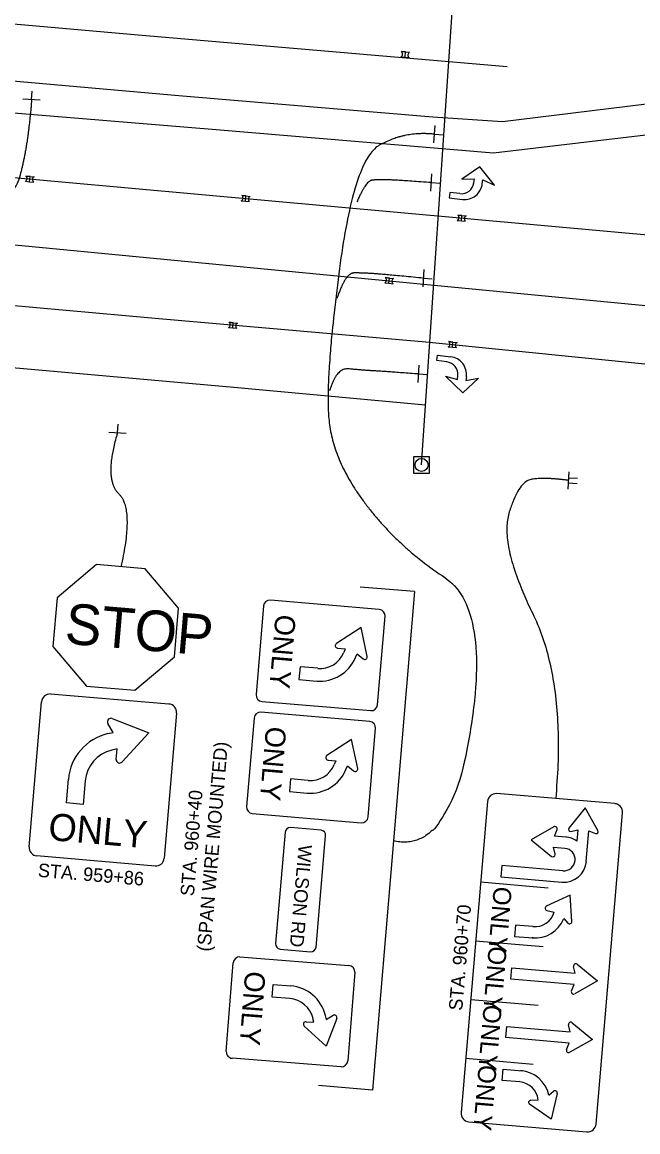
# Model space of a CAD drawing. Extents: x 1847379 to 1850904, y 217032 to 220169.
# Drawn here: x 1850096.6 to 1850210.2, y 218575.8 to 218780.5 of the extents above; entities that cross this region are included whole.
import ezdxf

# ---------------------------------------------------------------- set-up
doc = ezdxf.new("R2010")
doc.units = 0
for name, color, linetype in [('PM_P_Cells', 7, 'Continuous'), ('PM_P_Channelizing_Line', 7, 'Continuous'), ('PM_P_Edge_Line', 7, 'Continuous'), ('PM_P_Lane_Line', 7, 'Continuous'), ('SG_X_Poles', 7, 'Continuous'), ('SN_X_Public', 7, 'Continuous'), ('SN_X_Text', 7, 'Continuous')]:
    doc.layers.add(name, color=color, linetype=linetype)

msp = doc.modelspace()

# ---------------------------------------------------------------- linework, layer by layer
at = {"layer": 'PM_P_Cells'}
for p, q in [((1850166.51, 218774.14), (1850167.28, 218774.07)), ((1850166.51, 218774.14), (1850167.28, 218774.07)), ((1850167.36, 218775.04), (1850166.6, 218775.11)), ((1850166.6, 218775.11), (1850167.36, 218775.04)), ((1850167.28, 218774.07), (1850167.36, 218775.04)), ((1850167.28, 218774.07), (1850168.04, 218774)), ((1850167.36, 218775.04), (1850168.13, 218774.98)), ((1850181.1, 218753.83), (1850177.76, 218751.54)), ((1850183.76, 218750.49), (1850181.1, 218753.83)), ((1850098.09, 218752.07), (1850097.32, 218752.14)), ((1850097.32, 218752.14), (1850098.09, 218752.07)), ((1850098, 218751.1), (1850098.09, 218752.07)), ((1850098.09, 218752.07), (1850098.85, 218752)), ((1850175.82, 218751.44), (1850175.82, 218751.44)), ((1850177.76, 218751.54), (1850180.03, 218751.61)), ((1850180.03, 218751.61), (1850179.94, 218750.91)), ((1850097.23, 218751.17), (1850098, 218751.1)), ((1850097.23, 218751.17), (1850098, 218751.1)), ((1850098, 218751.1), (1850098.77, 218751.03)), ((1850181.53, 218750.75), (1850181.61, 218751.42)), ((1850181.61, 218751.42), (1850183.76, 218750.49)), ((1850183.76, 218750.49), (1850183.76, 218750.49)), ((1850137.07, 218747.57), (1850137.84, 218747.5)), ((1850137.07, 218747.57), (1850137.84, 218747.5)), ((1850137.93, 218748.47), (1850137.16, 218748.54)), ((1850137.16, 218748.54), (1850137.93, 218748.47)), ((1850137.84, 218747.5), (1850137.93, 218748.47)), ((1850137.84, 218747.5), (1850138.6, 218747.43)), ((1850137.93, 218748.47), (1850138.69, 218748.4)), ((1850175.54, 218749.12), (1850175.42, 218748.13)), ((1850175.42, 218748.13), (1850177.88, 218747.83)), ((1850177.39, 218748.9), (1850175.54, 218749.12)), ((1850176.91, 218743.96), (1850177.68, 218743.89)), ((1850176.91, 218743.96), (1850177.68, 218743.89)), ((1850177.76, 218744.87), (1850177, 218744.94)), ((1850177, 218744.94), (1850177.76, 218744.87)), ((1850177.68, 218743.89), (1850177.76, 218744.87)), ((1850177.68, 218743.89), (1850178.44, 218743.82)), ((1850177.76, 218744.87), (1850178.53, 218744.8)), ((1850164.39, 218733.33), (1850163.63, 218733.4)), ((1850163.63, 218733.4), (1850164.39, 218733.33)), ((1850164.31, 218732.35), (1850164.39, 218733.33)), ((1850164.39, 218733.33), (1850165.16, 218733.26)), ((1850163.54, 218732.42), (1850164.31, 218732.35)), ((1850163.54, 218732.42), (1850164.31, 218732.35)), ((1850164.31, 218732.35), (1850165.07, 218732.28)), ((1850135.57, 218725.09), (1850134.81, 218725.16)), ((1850134.81, 218725.16), (1850135.57, 218725.09)), ((1850135.49, 218724.12), (1850135.57, 218725.09)), ((1850135.57, 218725.09), (1850136.34, 218725.02)), ((1850134.72, 218724.19), (1850135.49, 218724.12)), ((1850134.72, 218724.19), (1850135.49, 218724.12)), ((1850135.49, 218724.12), (1850136.25, 218724.05)), ((1850176.11, 218721.52), (1850175.34, 218721.59)), ((1850175.34, 218721.59), (1850176.11, 218721.52)), ((1850176.02, 218720.55), (1850176.11, 218721.52)), ((1850176.11, 218721.52), (1850176.88, 218721.45)), ((1850173.14, 218718.08), (1850173.26, 218719.07)), ((1850173.26, 218719.07), (1850175.72, 218718.79)), ((1850175.25, 218720.62), (1850176.02, 218720.55)), ((1850175.25, 218720.62), (1850176.02, 218720.55)), ((1850176.02, 218720.55), (1850176.79, 218720.48)), ((1850174.99, 218717.86), (1850173.14, 218718.08)), ((1850172.88, 218715.76), (1850172.88, 218715.76)), ((1850177.94, 218712.16), (1850174.74, 218715.21)), ((1850174.74, 218715.21), (1850176.93, 218714.62)), ((1850176.93, 218714.62), (1850177.01, 218715.32)), ((1850180.82, 218714.85), (1850177.94, 218712.16)), ((1850178.6, 218715.1), (1850178.52, 218714.44)), ((1850178.52, 218714.44), (1850180.82, 218714.85)), ((1850180.82, 218714.85), (1850180.82, 218714.85))]:
    msp.add_line(p, q, dxfattribs=at)
for centre, radius, start, end in [((1850166.25, 218774.66), 0.576, 296.8063, 52.8586), ((1850166.25, 218774.66), 0.576, 296.8063, 52.8586), ((1850168.39, 218774.46), 0.576, 116.8063, 232.8586), ((1850096.97, 218751.68), 0.576, 296.8063, 52.8586), ((1850096.97, 218751.68), 0.576, 296.8063, 52.8586), ((1850099.11, 218751.49), 0.576, 116.8063, 232.8586), ((1850177.66, 218751.18), 2.3, 263.1824, 353.1824), ((1850178.27, 218751.09), 3.28, 263.1824, 354.0909), ((1850136.81, 218748.08), 0.576, 296.8063, 52.8586), ((1850136.81, 218748.08), 0.576, 296.8063, 52.8586), ((1850138.95, 218747.89), 0.576, 116.8063, 232.8586), ((1850176.65, 218744.48), 0.576, 296.8063, 52.8586), ((1850176.65, 218744.48), 0.576, 296.8063, 52.8586), ((1850178.79, 218744.28), 0.576, 116.8063, 232.8586), ((1850163.28, 218732.94), 0.576, 296.8063, 52.8586), ((1850163.28, 218732.94), 0.576, 296.8063, 52.8586), ((1850165.42, 218732.74), 0.576, 116.8063, 232.8586), ((1850134.46, 218724.7), 0.576, 296.8063, 52.8586), ((1850134.46, 218724.7), 0.576, 296.8063, 52.8586), ((1850136.6, 218724.51), 0.576, 116.8063, 232.8586), ((1850174.99, 218721.13), 0.576, 296.8063, 52.8586), ((1850174.99, 218721.13), 0.576, 296.8063, 52.8586), ((1850177.13, 218720.94), 0.576, 116.8063, 232.8586), ((1850175.34, 218715.53), 3.28, 352.5446, 83.453), ((1850174.73, 218715.58), 2.3, 353.453, 83.453)]:
    msp.add_arc(centre, radius, start, end, dxfattribs=at)
at = {"layer": 'PM_P_Channelizing_Line'}
for points in [[(1850652.98, 218698.12), (1850615.27, 218701.75), (1850564.66, 218706.78), (1850513.12, 218712.05), (1850461.3, 218717.14), (1850408.88, 218722.34), (1850360.86, 218727.03), (1850313.39, 218731.82), (1850265.8, 218736.37), (1849979.48, 218762.27)], [(1850650.65, 218674.09), (1850566.02, 218682.53), (1850518.02, 218687.39), (1850471.03, 218692.07), (1850419.06, 218697.16), (1850371.65, 218702.19), (1850311.6, 218707.75), (1850264.65, 218712.06), (1850215.84, 218717), (1850171.13, 218721.51), (1850121.19, 218725.85), (1850066.37, 218730.8), (1850014.99, 218735.41), (1849965.69, 218739.72), (1849914.21, 218744.36), (1849896.49, 218746.14)]]:
    msp.add_lwpolyline(points, dxfattribs=at)
at = {"layer": 'PM_P_Edge_Line'}
for p, q in [((1850068.7, 218772.02), (1850126.22, 218766.95)), ((1850185.27, 218762.22), (1850232.15, 218767.99)), ((1850126.22, 218766.95), (1850172.4, 218763.06)), ((1850132.45, 218760.65), (1850081.59, 218764.87)), ((1850172.4, 218763.06), (1850185.27, 218762.22)), ((1850235.11, 218762.44), (1850183.58, 218756.39)), ((1850183.58, 218756.39), (1850132.45, 218760.65))]:
    msp.add_line(p, q, dxfattribs=at)
msp.add_lwpolyline([(1849832.17, 218750.77), (1849894.17, 218734.94), (1849941.43, 218730.63), (1849992.34, 218726.14), (1850039.4, 218721.8), (1850086.44, 218717.54), (1850135.69, 218713.18), (1850171.07, 218709.94)], dxfattribs=at)
at = {"layer": 'PM_P_Lane_Line'}
msp.add_line((1849881.96, 218760.04), (1850650.78, 218685.87), dxfattribs=at)
msp.add_lwpolyline([(1849608.14, 218816.84), (1849659.46, 218813.21), (1849709.31, 218809.62), (1849760.21, 218805.9), (1849807.22, 218802.44), (1849857.63, 218799.12), (1849906.82, 218795.7), (1849957.46, 218791.82), (1850014.55, 218787.19), (1850067.13, 218782.71), (1850118.03, 218778.2), (1850167.47, 218773.95), (1850186.14, 218772.34)], dxfattribs=at)
at = {"layer": 'SG_X_Poles'}
msp.add_lwpolyline([(1850168.82, 218697.33), (1850171.82, 218697.33), (1850171.82, 218700.33), (1850168.82, 218700.33)], close=True, dxfattribs=at)
msp.add_circle((1850170.32, 218698.83), 1.2, dxfattribs=at)
at = {"layer": 'SN_X_Public'}
for p, q in [((1850170.32, 218698.83), (1850177.96, 218812.22)), ((1850098.38, 218766.24), (1850098.49, 218767.83)), ((1850099.98, 218766.13), (1850096.78, 218766.34)), ((1850172.61, 218758.27), (1850172.82, 218761.46)), ((1850172.72, 218759.86), (1850174.31, 218759.76)), ((1850172.03, 218749.33), (1850172.24, 218752.53)), ((1850172.14, 218750.93), (1850173.73, 218750.82)), ((1850170.61, 218731.71), (1850170.82, 218734.9)), ((1850170.71, 218733.3), (1850172.31, 218733.2)), ((1850169.7, 218714.03), (1850169.91, 218717.22)), ((1850169.81, 218715.62), (1850171.4, 218715.52)), ((1850115.81, 218704.64), (1850112.62, 218704.85)), ((1850114.22, 218704.75), (1850114.32, 218706.34)), ((1850197.36, 218694.39), (1850197.55, 218697.59)), ((1850197.48, 218696.47), (1850199.08, 218696.37)), ((1850197.42, 218695.51), (1850199.02, 218695.41)), ((1850197.45, 218695.99), (1850197.45, 218695.99)), ((1850110.38, 218680.44), (1850103.08, 218674.29)), ((1850119.35, 218679.68), (1850110.38, 218680.44)), ((1850125.5, 218672.39), (1850119.35, 218679.68)), ((1850103.08, 218674.29), (1850102.32, 218665.32)), ((1850124.74, 218663.42), (1850125.5, 218672.39)), ((1850159.19, 218668.86), (1850154.61, 218665.89)), ((1850160.3, 218663.52), (1850159.19, 218668.86)), ((1850102.32, 218665.32), (1850108.48, 218658.02)), ((1850117.45, 218657.26), (1850124.74, 218663.42)), ((1850154.82, 218665.03), (1850156.26, 218664.9)), ((1850156.26, 218664.9), (1850155.98, 218664.21)), ((1850158.14, 218663.31), (1850158.43, 218664)), ((1850158.43, 218664), (1850159.53, 218663.06)), ((1850147.91, 218661.58), (1850147.71, 218659.25)), ((1850151.18, 218661.31), (1850147.91, 218661.58)), ((1850108.48, 218658.02), (1850117.45, 218657.26)), ((1850147.71, 218659.25), (1850150.98, 218658.97)), ((1850113.44, 218649.48), (1850112.46, 218651.15)), ((1850113.23, 218652.05), (1850120, 218649.39)), ((1850112.47, 218649.26), (1850113.44, 218649.48)), ((1850120, 218649.39), (1850115.07, 218644.04)), ((1850157.43, 218648.18), (1850152.85, 218645.22)), ((1850158.54, 218642.84), (1850157.43, 218648.18)), ((1850114.14, 218646.44), (1850113.17, 218646.22)), ((1850113.99, 218644.51), (1850114.14, 218646.44)), ((1850153.06, 218644.36), (1850154.51, 218644.22)), ((1850154.51, 218644.22), (1850154.22, 218643.54)), ((1850156.38, 218642.63), (1850156.67, 218643.32)), ((1850156.67, 218643.32), (1850157.78, 218642.39)), ((1850146.15, 218640.91), (1850145.95, 218638.57)), ((1850149.42, 218640.63), (1850146.15, 218640.91)), ((1850104.79, 218636.47), (1850105.16, 218640.83)), ((1850108.27, 218640.56), (1850107.9, 218636.2)), ((1850145.95, 218638.57), (1850149.22, 218638.29)), ((1850107.9, 218636.2), (1850104.79, 218636.47)), ((1850200.53, 218635.54), (1850197.51, 218631.83)), ((1850202.87, 218631.37), (1850200.53, 218635.54)), ((1850194.76, 218632.07), (1850190.56, 218629.67)), ((1850194.86, 218630.35), (1850195.35, 218631.55)), ((1850197.88, 218631.23), (1850199.14, 218631.48)), ((1850199.14, 218631.48), (1850198.96, 218629.44)), ((1850200.73, 218625.67), (1850201.21, 218631.3)), ((1850201.21, 218631.3), (1850202.41, 218630.84)), ((1850190.56, 218629.67), (1850194.29, 218626.61)), ((1850196.94, 218630.18), (1850194.86, 218630.35)), ((1850194.96, 218627.02), (1850194.69, 218628.28)), ((1850194.69, 218628.28), (1850196.76, 218628.1)), ((1850185.14, 218624.91), (1850184.97, 218622.83)), ((1850184.97, 218622.83), (1850196.23, 218621.87)), ((1850181.23, 218621.89), (1850193.68, 218620.83)), ((1850197.75, 218619.44), (1850193.35, 218617.42)), ((1850198.06, 218614.61), (1850197.75, 218619.44)), ((1850193.43, 218616.64), (1850194.79, 218616.31)), ((1850196.59, 218615.14), (1850197.33, 218614.31)), ((1850187.66, 218613.92), (1850187.48, 218611.84)), ((1850190.88, 218613.65), (1850187.66, 218613.92)), ((1850180.31, 218611.04), (1850192.76, 218609.99)), ((1850187.48, 218611.84), (1850190.97, 218611.55)), ((1850190.97, 218611.55), (1850190.71, 218611.56)), ((1850198.65, 218605.04), (1850198.37, 218606.3)), ((1850199.04, 218606.71), (1850202.78, 218603.65)), ((1850186.81, 218603.96), (1850186.99, 218606.03)), ((1850186.99, 218606.03), (1850198.65, 218605.04)), ((1850142.75, 218600.62), (1850142.93, 218602.95)), ((1850142.93, 218602.95), (1850146.21, 218602.7)), ((1850198.47, 218602.97), (1850186.81, 218603.96)), ((1850197.99, 218601.77), (1850198.47, 218602.97)), ((1850202.78, 218603.65), (1850198.58, 218601.25)), ((1850146.02, 218600.36), (1850142.75, 218600.62)), ((1850179.39, 218600.2), (1850191.84, 218599.14)), ((1850149.02, 218596.1), (1850150.46, 218596)), ((1850150.46, 218596), (1850150.29, 218596.72)), ((1850152.57, 218597.26), (1850152.74, 218596.54)), ((1850154.67, 218596.71), (1850152.71, 218591.62)), ((1850152.74, 218596.54), (1850153.99, 218597.28)), ((1850198.13, 218595.92), (1850201.86, 218592.85)), ((1850152.71, 218591.62), (1850148.67, 218595.28)), ((1850185.9, 218593.16), (1850186.07, 218595.24)), ((1850186.07, 218595.24), (1850197.73, 218594.25)), ((1850197.73, 218594.25), (1850197.45, 218595.5)), ((1850197.56, 218592.17), (1850185.9, 218593.16)), ((1850197.07, 218590.98), (1850197.56, 218592.17)), ((1850201.86, 218592.85), (1850197.66, 218590.46)), ((1850178.47, 218589.35), (1850190.92, 218588.29)), ((1850185.23, 218585.27), (1850185.4, 218587.35)), ((1850185.4, 218587.35), (1850188.89, 218587.05)), ((1850188.89, 218587.05), (1850188.63, 218587.08)), ((1850188.45, 218585), (1850185.23, 218585.27)), ((1850190.46, 218581.62), (1850191.86, 218581.71)), ((1850193.82, 218582.57), (1850194.7, 218583.26)), ((1850195.36, 218582.84), (1850194.24, 218578.13)), ((1850194.24, 218578.13), (1850190.25, 218580.86))]:
    msp.add_line(p, q, dxfattribs=at)
for points in [[(1850162.53, 218672.18), (1850142.44, 218673.89)], [(1850141.18, 218672.82), (1850139.79, 218656.47)], [(1850162.21, 218654.57), (1850163.6, 218670.91)], [(1850101.89, 218656.58), (1850123.69, 218654.73)], [(1850097.93, 218628.37), (1850100.2, 218655.15)], [(1850160.77, 218651.51), (1850140.69, 218653.21)], [(1850140.86, 218655.2), (1850160.94, 218653.5)], [(1850125.12, 218653.04), (1850122.84, 218626.26)], [(1850139.42, 218652.14), (1850138.03, 218635.79)], [(1850160.45, 218633.89), (1850161.84, 218650.24)], [(1850205.98, 218636.34), (1850184.18, 218638.19)], [(1850182.49, 218636.76), (1850177.62, 218579.33)], [(1850139.1, 218634.53), (1850159.19, 218632.82)], [(1850202.53, 218577.22), (1850207.4, 218634.65)], [(1850145.16, 218631.07), (1850143.39, 218610.52)], [(1850151.78, 218631.44), (1850146.17, 218631.92)], [(1850150.86, 218609.88), (1850152.63, 218630.43)], [(1850121.15, 218624.83), (1850099.36, 218626.68)], [(1850196.41, 218623.95), (1850193.64, 218624.18), (1850185.14, 218624.91)], [(1850144.24, 218609.51), (1850149.84, 218609.02)], [(1850134.3, 218590.62), (1850135.57, 218606.97)], [(1850136.82, 218608.05), (1850156.92, 218606.5)], [(1850158, 218605.24), (1850156.73, 218588.88)], [(1850155.47, 218587.8), (1850135.38, 218589.36)], [(1850179.04, 218577.64), (1850200.84, 218575.79)]]:
    msp.add_lwpolyline(points, dxfattribs=at)
for centre, radius, start, end in [((1850142.34, 218672.72), 1.17, 85.1482, 175.1482), ((1850162.43, 218671.01), 1.17, 355.1482, 85.1482), ((1850154.86, 218665.5), 0.469, 122.9024, 264.6742), ((1850151.58, 218666.05), 4.77, 265.1482, 337.2869), ((1850159.84, 218663.42), 0.469, 229.9417, 11.7135), ((1850151.58, 218666.05), 7.11, 265.1482, 337.2907), ((1850101.76, 218655.02), 1.56, 85.1482, 175.1482), ((1850140.96, 218656.37), 1.17, 175.1482, 265.1482), ((1850123.56, 218653.17), 1.56, 355.1482, 85.1482), ((1850140.59, 218652.04), 1.17, 85.1482, 175.1482), ((1850161.04, 218654.67), 1.17, 265.1482, 355.1482), ((1850113, 218651.47), 0.625, 68.5828, 210.3546), ((1850160.67, 218650.34), 1.17, 355.1482, 85.1482), ((1850114.6, 218640.02), 9.48, 103.0056, 175.1482), ((1850114.6, 218640.02), 6.35, 103.0095, 175.1482), ((1850153.11, 218644.83), 0.469, 122.9024, 264.6742), ((1850114.61, 218644.46), 0.625, 175.6221, 317.3939), ((1850149.82, 218645.38), 4.77, 265.1482, 337.2869), ((1850149.82, 218645.38), 7.11, 265.1482, 337.2907), ((1850158.08, 218642.75), 0.469, 229.9417, 11.7135), ((1850184.05, 218636.63), 1.56, 85.1482, 175.1482), ((1850139.2, 218635.7), 1.17, 175.1482, 265.1482), ((1850205.84, 218634.78), 1.56, 355.1482, 85.1482), ((1850159.29, 218633.99), 1.17, 265.1482, 355.1482), ((1850146.09, 218630.99), 0.937, 85.0678, 175.0678), ((1850151.7, 218630.51), 0.937, 355.0678, 85.0678), ((1850194.96, 218631.7), 0.417, 337.7863, 119.6644), ((1850197.8, 218631.59), 0.372, 140.9571, 281.1925), ((1850202.55, 218631.19), 0.372, 249.1038, 29.3392), ((1850196.58, 218626.02), 4.17, 55.1391, 85.1482), ((1850099.49, 218628.24), 1.56, 175.1482, 265.1482), ((1850194.56, 218626.93), 0.417, 230.6319, 5.9155), ((1850194.56, 218626.93), 0.417, 5.9155, 12.51), ((1850196.58, 218626.02), 2.08, 265.1482, 85.1482), ((1850121.29, 218626.39), 1.56, 265.1482, 355.1482), ((1850196.58, 218626.02), 4.17, 265.1482, 355.1482), ((1850191.2, 218617.38), 3.75, 265.1482, 343.3714), ((1850193.53, 218617.04), 0.417, 114.6554, 256.5335), ((1850191.2, 218617.38), 5.84, 265.1482, 337.3801), ((1850197.64, 218614.59), 0.417, 221.8098, 3.6879), ((1850144.32, 218610.44), 0.938, 175.0678, 265.0678), ((1850149.92, 218609.96), 0.937, 265.0678, 355.0678), ((1850136.73, 218606.88), 1.17, 85.5744, 175.5744), ((1850156.83, 218605.33), 1.17, 355.5744, 85.5744), ((1850198.78, 218606.39), 0.417, 50.6319, 192.51), ((1850145.66, 218595.61), 7.11, 13.4319, 85.5744), ((1850145.66, 218595.61), 4.77, 13.4357, 85.5744), ((1850198.37, 218601.62), 0.417, 157.7863, 299.6644), ((1850148.99, 218595.63), 0.469, 86.0484, 227.8202), ((1850154.23, 218596.88), 0.469, 339.0091, 120.7809), ((1850197.86, 218595.6), 0.417, 50.6319, 192.51), ((1850135.47, 218590.52), 1.17, 175.5744, 265.5744), ((1850197.46, 218590.82), 0.417, 157.7863, 299.6644), ((1850155.56, 218588.97), 1.17, 265.5744, 355.5744), ((1850188.13, 218581.26), 5.84, 12.9162, 85.1482), ((1850188.13, 218581.26), 3.75, 6.9249, 85.1482), ((1850190.49, 218581.21), 0.417, 93.7628, 235.6409), ((1850194.95, 218582.93), 0.417, 346.6084, 128.4865), ((1850179.17, 218579.2), 1.56, 175.1482, 265.1482), ((1850200.97, 218577.35), 1.56, 265.1482, 355.1482)]:
    msp.add_arc(centre, radius, start, end, dxfattribs=at)
at = {"layer": 'SN_X_Text'}
for p, q in [((1850169, 218675.48), (1850159.03, 218676.31)), ((1850169, 218675.48), (1850161.3, 218583.48)), ((1850161.3, 218583.48), (1850151.33, 218584.31))]:
    msp.add_line(p, q, dxfattribs=at)
for points in [[(1850098.38, 218766.24), (1850097.65, 218756.86), (1850094.34, 218746.14), (1850067.97, 218743.17), (1850049.26, 218735.39), (1850044.16, 218707.57)], [(1850172.72, 218759.86), (1850167.09, 218760.47), (1850157.83, 218755.07), (1850152.55, 218715.1), (1850153.87, 218699.77), (1850165.88, 218683.81), (1850183.04, 218672.56), (1850175.63, 218626.98), (1850165.15, 218629.48)], [(1850172.14, 218750.93), (1850165.51, 218751.41), (1850162.28, 218751.51), (1850160.06, 218751.22), (1850158.41, 218747.39)], [(1850170.71, 218733.3), (1850163.49, 218734), (1850159.29, 218734.28), (1850156.3, 218734.24), (1850154.7, 218729.52)], [(1850169.81, 218715.62), (1850163.18, 218716.1), (1850159.23, 218716.34), (1850154.59, 218716.8), (1850153.37, 218712.53)], [(1850114.22, 218704.75), (1850111.63, 218696.24), (1850117.29, 218690.8), (1850114.86, 218680.06)], [(1850197.45, 218695.99), (1850192.81, 218696.6), (1850188.2, 218695.72), (1850184.68, 218684.05), (1850197.02, 218658.7), (1850195.08, 218637.26)]]:
    msp.add_open_spline(points, degree=2, dxfattribs=at)

# ---------------------------------------------------------------- texts
at = {"layer": 'SN_X_Public'}
for s, height, rotation, p in [('STOP', 7.5, 355.1482, (1850104.34, 218665.9)), ('ONLY', 3.75, 265.1482, (1850143.4, 218671.34)), ('ONLY', 3.75, 265.1482, (1850141.65, 218650.67)), ('ONLY', 5, 355.1482, (1850101.33, 218629.65)), ('WILSON RD', 2.5, 265.0678, (1850147.65, 218628.83)), ('ONLY', 3.333, 265.1482, (1850183.67, 218621.13)), ('ONLY', 3.333, 265.1482, (1850182.74, 218610.13)), ('ONLY', 3.75, 265.5744, (1850137.8, 218605.51)), ('ONLY', 3.333, 265.1482, (1850181.82, 218599.34)), ('ONLY', 3.333, 265.1482, (1850180.88, 218588.24))]:
    msp.add_text(s, height=height, rotation=rotation, dxfattribs=at).set_placement(p)
at = {"layer": 'SN_X_Text'}
for s, rotation, p in [('(SPAN WIRE MOUNTED)', 85.217, (1850131.37, 218608.99)), ('STA. 960+40', 85.217, (1850128.31, 218619.2)), ('STA. 959+86', 355.1482, (1850099.46, 218622.85)), ('STA. 960+70', 85.1482, (1850177.83, 218598.07))]:
    msp.add_text(s, height=2.5, rotation=rotation, dxfattribs=at).set_placement(p)

doc.saveas('drawing.dxf')
